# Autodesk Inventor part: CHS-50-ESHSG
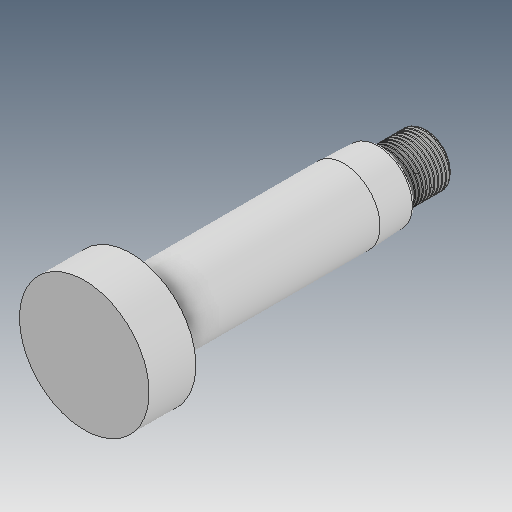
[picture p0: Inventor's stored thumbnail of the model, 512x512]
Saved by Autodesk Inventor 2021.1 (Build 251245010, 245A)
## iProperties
Created: 2019-04
Part Number: CHS-50-ESHSG
Material: Ogólny
Document SubType Name: Modeling
Designer: user
Density: 1 g/cm^3
Appearance: Domyślna
Author: user
Revision Number: ÈÎºÎ
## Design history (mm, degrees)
feature "ÊäÈë1"
node "Bryła1"
